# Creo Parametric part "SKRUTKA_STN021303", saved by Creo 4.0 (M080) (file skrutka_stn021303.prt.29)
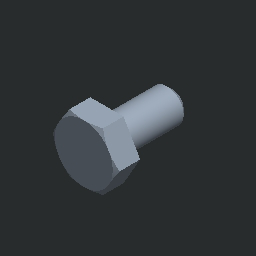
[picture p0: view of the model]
Units: Custom; MM, KILOGRAM, SECS
Materials in the file: OCEL_N

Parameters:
  MFG_WP_MATERIAL = "OCEL"
  NAZOV = "SKRUTKA_STN021303"
  NORMA = "STN 02 1303"
  PTC_MATERIAL_NAME = "OCEL_N"

Other parameters: HMOTNOST, HUSTOTA, D10, D0, D17, D19

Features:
  1. datum plane "DTM1"
  2. protrusion
  3. datum plane "DTM2"
  4. cut
  5. round
  6. chamfer
  7. datum plane "DTM3"
  8. datum plane "DTM4"

Other named items: BLIND

Layers: 1, 2, 3, 4, 5, 6, 7, 8, 9, 10, 11, 12, 13, 14, 15, 16, 17, 18, 19, 20, 21, 22, 23, 24, 25, 26, 27, 28, 29, 30, 31, 32

Family table entries: GENERIC, SKRUTKA_M5, SKRUTKA_STN021303, value(d_val), 2/ , value(i_val), SKRUTKA_M6, SKRUTKA_STN021303, 2/$, SKRUTKA_M8, SKRUTKA_STN021303, !/ , 2/*, SKRUTKA_M10, SKRUTKA_STN021303, !/$, 2/0, SKRUTKA_M12, SKRUTKA_STN021303, !/(, 2/ , 2/2, SKRUTKA_M16, SKRUTKA_STN021303, !/0, 2/$, 2/8, SKRUTKA_M20, SKRUTKA_STN021303, !/4, 2/*, 2/>, SKRUTKA_M24, SKRUTKA_STN021303, !/8, 2/., 2/B, # Pro/TABLE, [] S 92;, [] W 10;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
